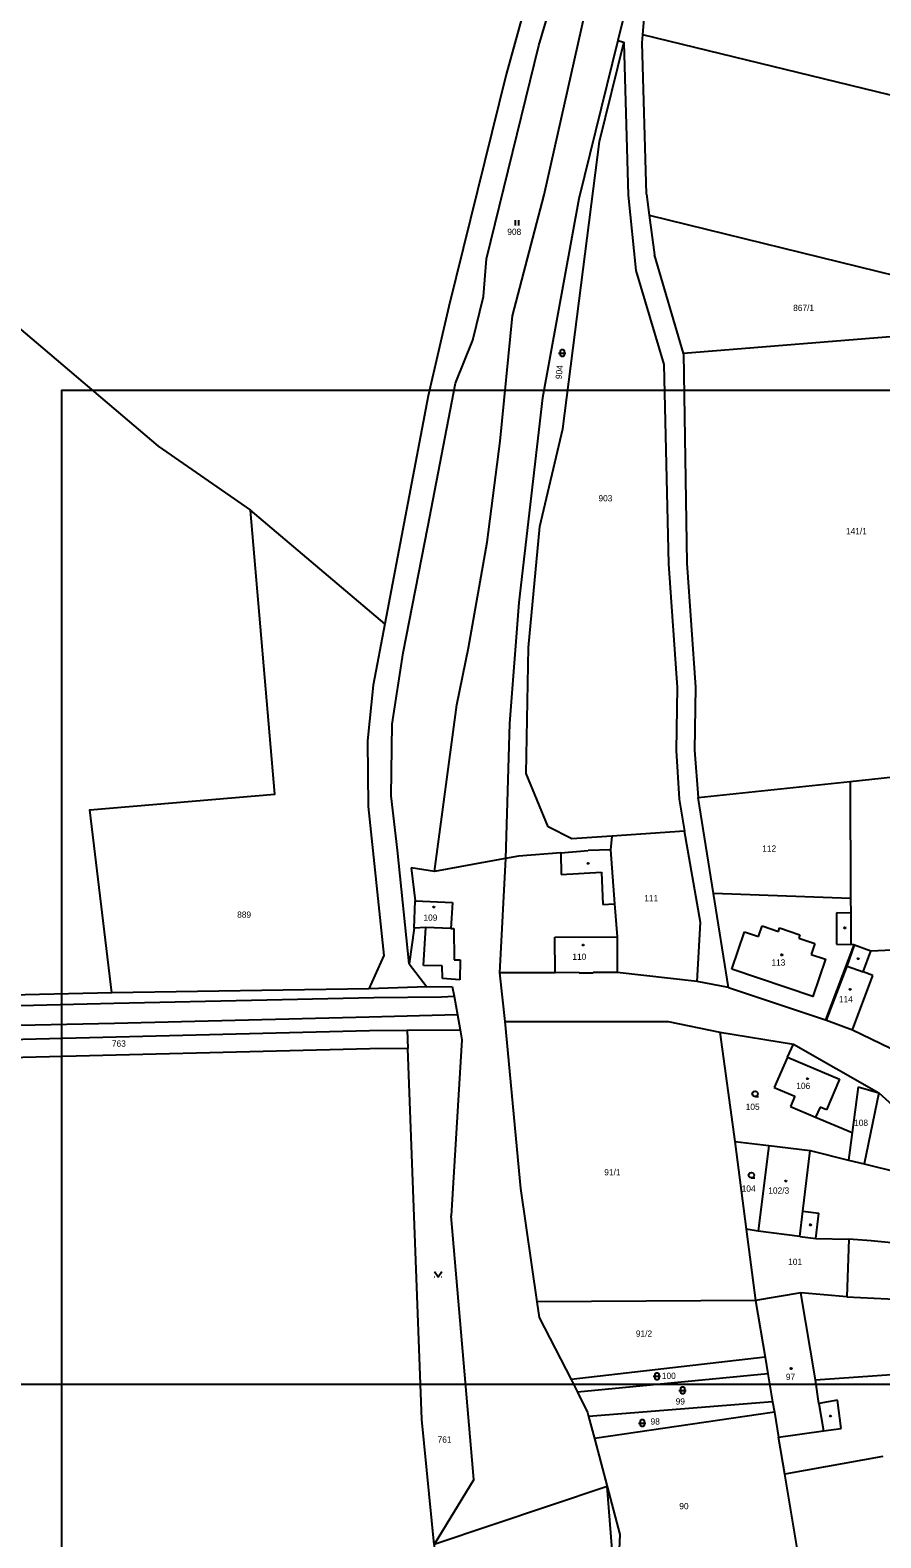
# Model space of a CAD drawing. Extents: x -812394 to -807601, y -1013097 to -1009266.
# Drawn here: x -810008.6 to -809776.7, y -1010812.8 to -1010401.8 of the extents above; entities that cross this region are included whole.
import ezdxf

# ---------------------------------------------------------------- set-up
doc = ezdxf.new("R2010")
doc.units = 0
for name, color, linetype in [('Default', 7, 'Continuous'), ('KLADY_ZMVM', 7, 'Continuous'), ('KN_HRANICE', 7, 'Continuous'), ('KN_KULTURY', 7, 'Continuous'), ('KN_PARCELY', 7, 'Continuous'), ('KN_SLUCKY', 7, 'Continuous'), ('LEGENDA', 7, 'Continuous'), ('obvod_stavby', 7, 'Continuous')]:
    doc.layers.add(name, color=color, linetype=linetype)

# ---------------------------------------------------------------- blocks, each defined once
blk = doc.blocks.new('304')
at = {"layer": 'Default'}
blk.add_lwpolyline([(0, 0), (-0.38, 0.1), (-0.65, 0.37), (-0.75, 0.74), (-0.65, 1.11), (-0.38, 1.38), (-0.01, 1.48), (0.36, 1.38), (0.63, 1.11), (0.73, 0.73), (0.63, 0.35), (0.36, 0.08), (-0.02, -0.02), (0.98, -0.02)], dxfattribs=at)
blk = doc.blocks.new('306')
at = {"layer": 'Default'}
for p, q in [((-0.5, 1.5), (-0.5, 0)), ((0.5, 0), (0.5, 1.5))]:
    blk.add_line(p, q, dxfattribs=at)
blk = doc.blocks.new('314')
at = {"layer": 'Default'}
for p, q in [((-0.95, 0), (-0.85, 0)), ((0.85, 0), (0.95, 0))]:
    blk.add_line(p, q, dxfattribs=at)
blk.add_lwpolyline([(-1, 1.5), (0, 0), (1, 1.5)], dxfattribs=at)
blk = doc.blocks.new('316')
at = {"layer": 'Default'}
for points in [[(-1, 1), (0.27, 1), (1, 1)], [(-0.5, 1.5), (-0.4, 1.79), (-0.15, 1.97), (0.16, 1.97), (0.41, 1.79), (0.51, 1.5), (0.51, 0.5), (0.41, 0.21), (0.16, 0.03), (-0.15, 0.03), (-0.4, 0.21), (-0.5, 0.5), (-0.5, 1.5)]]:
    blk.add_lwpolyline(points, dxfattribs=at)
blk = doc.blocks.new('402')
at = {"layer": 'Default'}
blk.add_lwpolyline([(0.09, 0.15), (0.18, 0), (0.09, -0.15), (-0.09, -0.15), (-0.18, 0), (-0.09, 0.15), (0.09, 0.15)], dxfattribs=at)

msp = doc.modelspace()

# ---------------------------------------------------------------- linework, layer by layer
at = {"layer": 'KLADY_ZMVM'}
msp.add_lwpolyline([(-810000, -1011000), (-810000, -1010500), (-809375, -1010500), (-809375, -1011000), (-809466.04, -1011000)], dxfattribs=at)
at = {"layer": 'KN_HRANICE'}
for p, q in [((-809864.27, -1010361.43), (-809878.82, -1010413.89)), ((-809869.89, -1010406.06), (-809858.75, -1010368.45)), ((-809842.4, -1010380.57), (-809848.37, -1010404.67)), ((-809841.57, -1010403.09), (-809840.96, -1010395.38)), ((-809841.74, -1010405.27), (-809841.57, -1010403.09)), ((-809714.42, -1010434.16), (-809841.57, -1010403.09)), ((-809884.23, -1010464.16), (-809869.89, -1010406.06)), ((-809848.37, -1010404.67), (-809859.05, -1010447.8)), ((-809853.38, -1010432.24), (-809846.74, -1010405.27)), ((-809848.37, -1010404.67), (-809846.74, -1010405.14)), ((-809846.74, -1010405.14), (-809846.74, -1010405.27)), ((-809846.74, -1010405.27), (-809845.6, -1010446.84)), ((-809840.6, -1010446.52), (-809841.74, -1010405.27)), ((-809878.82, -1010413.89), (-809894.45, -1010477.13)), ((-809863.41, -1010510.51), (-809853.38, -1010432.24)), ((-809859.05, -1010447.8), (-809868.93, -1010502.05)), ((-809845.6, -1010446.84), (-809843.49, -1010467.38)), ((-809840.6, -1010446.52), (-809839.82, -1010452.31)), ((-809839.82, -1010452.31), (-809838.38, -1010463.06)), ((-809839.82, -1010452.31), (-809731.16, -1010478.93)), ((-809885.03, -1010474.47), (-809884.23, -1010464.16)), ((-809830.46, -1010490), (-809838.38, -1010463.06)), ((-809843.49, -1010467.38), (-809835.86, -1010493.01)), ((-809894.45, -1010477.13), (-809900.14, -1010501.55)), ((-809887.91, -1010486.35), (-809885.03, -1010474.47)), ((-809892.66, -1010498.08), (-809887.91, -1010486.35)), ((-809763.21, -1010484.53), (-809830.46, -1010490)), ((-809830.46, -1010490), (-809829.59, -1010547.11)), ((-809835.86, -1010493.01), (-809834.59, -1010547.32)), ((-809900.15, -1010537.27), (-809892.66, -1010498.08)), ((-809900.14, -1010501.55), (-809911.91, -1010563.63)), ((-809868.93, -1010502.05), (-809875.4, -1010557.89)), ((-809869.64, -1010537.09), (-809863.41, -1010510.51)), ((-809911.91, -1010563.63), (-809948.53, -1010532.68)), ((-809906.93, -1010571.6), (-809900.15, -1010537.27)), ((-809872.78, -1010570.15), (-809869.64, -1010537.09)), ((-809834.59, -1010547.32), (-809832.23, -1010581.05)), ((-809829.59, -1010547.11), (-809827.23, -1010580.92)), ((-809875.4, -1010557.89), (-809877.92, -1010590.8)), ((-809911.91, -1010563.63), (-809915.08, -1010580.36)), ((-809909.95, -1010591.02), (-809906.93, -1010571.6)), ((-809873.36, -1010604.47), (-809872.78, -1010570.15)), ((-809915.08, -1010580.36), (-809916.6, -1010595.6)), ((-809832.23, -1010581.05), (-809832.51, -1010598.19)), ((-809827.23, -1010580.92), (-809827.51, -1010598.06)), ((-809910.22, -1010610.58), (-809909.95, -1010591.02)), ((-809877.92, -1010590.8), (-809879.03, -1010627.62)), ((-809916.6, -1010595.6), (-809916.47, -1010613.47)), ((-809832.51, -1010598.19), (-809831.62, -1010611.42)), ((-809827.51, -1010598.06), (-809826.5, -1010610.99)), ((-809867.35, -1010619), (-809873.36, -1010604.47)), ((-809785.03, -1010606.6), (-809746.74, -1010602.54)), ((-809826.5, -1010610.99), (-809785.03, -1010606.6)), ((-809785.03, -1010606.6), (-809784.91, -1010638.49)), ((-809916.47, -1010613.47), (-809912.17, -1010654.1)), ((-809908.47, -1010625.32), (-809910.22, -1010610.58)), ((-809831.62, -1010611.42), (-809830.2, -1010620.19)), ((-809822.29, -1010637.21), (-809826.5, -1010610.99)), ((-809860.96, -1010622.27), (-809867.35, -1010619)), ((-809850.01, -1010621.53), (-809860.96, -1010622.27)), ((-809850.01, -1010621.53), (-809850.38, -1010625.24)), ((-809830.2, -1010620.19), (-809850.01, -1010621.53)), ((-809825.85, -1010645.04), (-809830.2, -1010620.19)), ((-809905.25, -1010656.34), (-809908.47, -1010625.32)), ((-809863.92, -1010626.08), (-809875.47, -1010626.99)), ((-809863.92, -1010626.08), (-809856.43, -1010625.49)), ((-809850.38, -1010625.24), (-809856.43, -1010625.49)), ((-809850.38, -1010625.24), (-809849.27, -1010639.96)), ((-809898.33, -1010631.14), (-809904.71, -1010630.14)), ((-809904.71, -1010630.14), (-809903.64, -1010639.2)), ((-809884.55, -1010628.63), (-809898.33, -1010631.14)), ((-809879.03, -1010627.62), (-809884.55, -1010628.63)), ((-809879.03, -1010627.62), (-809880.69, -1010658.8)), ((-809875.47, -1010626.99), (-809879.03, -1010627.62)), ((-809784.91, -1010638.49), (-809822.29, -1010637.21)), ((-809818.18, -1010662.82), (-809822.29, -1010637.21)), ((-809784.91, -1010638.49), (-809784.89, -1010642.49)), ((-809903.91, -1010646.62), (-809903.64, -1010639.2)), ((-809903.64, -1010639.2), (-809893.45, -1010639.62)), ((-809893.45, -1010639.62), (-809893.9, -1010646.74)), ((-809849.27, -1010639.96), (-809848.59, -1010648.97)), ((-809784.89, -1010642.49), (-809784.86, -1010651.09)), ((-809903.91, -1010646.62), (-809905.25, -1010656.34)), ((-809900.74, -1010646.45), (-809903.91, -1010646.62)), ((-809901.36, -1010656.81), (-809900.74, -1010646.45)), ((-809893.9, -1010646.74), (-809893.14, -1010646.74)), ((-809893.14, -1010646.74), (-809892.97, -1010655.26)), ((-809826.78, -1010661.18), (-809825.85, -1010645.04)), ((-809848.59, -1010648.97), (-809848.53, -1010658.67)), ((-809912.17, -1010654.1), (-809916.25, -1010663.18)), ((-809784.01, -1010651.14), (-809791.73, -1010671.61)), ((-809784.01, -1010651.14), (-809784.86, -1010651.09)), ((-809783.82, -1010651.21), (-809784.01, -1010651.14)), ((-809779.36, -1010652.87), (-809783.82, -1010651.21)), ((-809773.49, -1010652.65), (-809779.36, -1010652.87)), ((-809905.25, -1010656.34), (-809900.5, -1010662.65)), ((-809896.28, -1010656.85), (-809901.36, -1010656.81)), ((-809896.15, -1010660.38), (-809896.28, -1010656.85)), ((-809892.97, -1010655.26), (-809891.34, -1010655.24)), ((-809891.34, -1010655.24), (-809891.49, -1010660.73)), ((-809865.45, -1010658.79), (-809880.69, -1010658.8)), ((-809880.69, -1010658.8), (-809879.15, -1010672.04)), ((-809858.96, -1010658.74), (-809865.45, -1010658.79)), ((-809858.96, -1010658.89), (-809858.96, -1010658.74)), ((-809855.08, -1010658.87), (-809858.96, -1010658.89)), ((-809848.53, -1010658.67), (-809855.08, -1010658.72)), ((-809855.08, -1010658.72), (-809855.08, -1010658.87)), ((-809826.78, -1010661.18), (-809848.53, -1010658.67)), ((-809916.25, -1010663.18), (-809986.36, -1010664.25)), ((-809900.5, -1010662.65), (-809916.25, -1010663.18)), ((-809900.5, -1010662.65), (-809893.53, -1010662.52)), ((-809891.49, -1010660.73), (-809896.15, -1010660.38)), ((-809893.53, -1010662.52), (-809893.05, -1010665.19)), ((-809818.18, -1010662.82), (-809826.78, -1010661.18)), ((-809818.18, -1010662.82), (-809791.73, -1010671.61)), ((-809986.36, -1010664.25), (-810055.49, -1010665.89)), ((-809893.05, -1010665.19), (-809892.14, -1010670.27)), ((-809892.14, -1010670.27), (-809891.41, -1010674.3)), ((-810054.08, -1010677.99), (-809916.11, -1010674.55)), ((-809916.11, -1010674.55), (-809905.86, -1010674.45)), ((-809905.86, -1010674.45), (-809891.41, -1010674.3)), ((-809905.86, -1010674.45), (-809905.67, -1010679.45)), ((-809891.41, -1010674.3), (-809890.92, -1010677.02)), ((-809879.15, -1010672.04), (-809834.64, -1010672.02)), ((-809879.15, -1010672.04), (-809874.93, -1010717.6)), ((-809834.64, -1010672.02), (-809820.53, -1010674.93)), ((-809820.53, -1010674.93), (-809816.51, -1010704.77)), ((-809820.53, -1010674.93), (-809800.51, -1010678.2)), ((-809791.73, -1010671.61), (-809791.45, -1010671.71)), ((-809791.45, -1010671.71), (-809784.4, -1010674.33)), ((-809784.4, -1010674.33), (-809774.04, -1010679.33)), ((-809916.02, -1010679.55), (-810053.85, -1010682.99)), ((-809905.67, -1010679.45), (-809916.02, -1010679.55)), ((-809901.85, -1010780.54), (-809905.67, -1010679.45)), ((-809890.92, -1010677.02), (-809893.8, -1010725.05)), ((-809802.14, -1010681.76), (-809800.51, -1010678.2)), ((-809800.51, -1010678.2), (-809777.22, -1010691.48)), ((-809802.14, -1010681.76), (-809805.72, -1010690.09)), ((-809805.72, -1010690.09), (-809800.16, -1010692.42)), ((-809782.82, -1010689.83), (-809784.46, -1010702.29)), ((-809782.82, -1010689.83), (-809777.22, -1010691.48)), ((-809777.22, -1010691.48), (-809781.21, -1010710.87)), ((-809777.22, -1010691.48), (-809766.01, -1010701.62)), ((-809800.16, -1010692.42), (-809801.34, -1010695.22)), ((-809801.34, -1010695.22), (-809794.45, -1010698.17)), ((-809794.45, -1010698.17), (-809784.46, -1010702.29)), ((-809784.46, -1010702.29), (-809785.46, -1010709.82)), ((-809816.51, -1010704.77), (-809813.43, -1010728.67)), ((-809816.51, -1010704.77), (-809807.17, -1010705.86)), ((-809807.17, -1010705.86), (-809810.15, -1010729.19)), ((-809807.17, -1010705.86), (-809795.91, -1010707.24)), ((-809797.91, -1010723.76), (-809795.91, -1010707.24)), ((-809795.91, -1010707.24), (-809785.46, -1010709.82)), ((-809785.46, -1010709.82), (-809781.21, -1010710.87)), ((-809781.21, -1010710.87), (-809771.66, -1010713.22)), ((-809874.93, -1010717.6), (-809870.46, -1010748.48)), ((-809798.74, -1010730.64), (-809797.91, -1010723.76)), ((-809887.66, -1010796.86), (-809893.8, -1010725.05)), ((-809813.43, -1010728.67), (-809810.87, -1010748.08)), ((-809810.15, -1010729.19), (-809813.43, -1010728.67)), ((-809798.74, -1010730.64), (-809810.15, -1010729.19)), ((-809798.74, -1010730.64), (-809794.37, -1010731.2)), ((-809794.37, -1010731.2), (-809785.42, -1010731.43)), ((-809785.42, -1010731.43), (-809785.91, -1010747.13)), ((-809779.32, -1010731.85), (-809785.42, -1010731.43)), ((-809752.63, -1010734.46), (-809779.32, -1010731.85)), ((-809810.87, -1010748.08), (-809870.46, -1010748.48)), ((-809870.46, -1010748.48), (-809869.85, -1010752.77)), ((-809798.52, -1010745.99), (-809810.87, -1010748.08)), ((-809810.87, -1010748.08), (-809808.24, -1010763.58)), ((-809785.91, -1010747.13), (-809798.52, -1010745.99)), ((-809794.5, -1010769.7), (-809798.52, -1010745.99)), ((-809785.91, -1010747.13), (-809765.89, -1010748.07)), ((-809869.85, -1010752.77), (-809861.14, -1010769.64)), ((-809808.24, -1010763.58), (-809861.14, -1010769.64)), ((-809808.24, -1010763.58), (-809807.48, -1010768.06)), ((-809861.14, -1010769.64), (-809859.41, -1010773.1)), ((-809807.48, -1010768.06), (-809859.41, -1010773.1)), ((-809807.48, -1010768.06), (-809806.19, -1010775.7)), ((-809794.5, -1010769.7), (-809750.96, -1010766.66)), ((-809793.54, -1010776.17), (-809794.5, -1010769.7)), ((-809859.41, -1010773.1), (-809856.66, -1010778.59)), ((-809806.19, -1010775.7), (-809856.35, -1010779.75)), ((-809806.19, -1010775.7), (-809805.71, -1010778.53)), ((-809788.53, -1010775.31), (-809793.54, -1010776.17)), ((-809787.51, -1010782.96), (-809788.53, -1010775.31)), ((-809898.47, -1010814.6), (-809901.85, -1010780.54)), ((-809856.66, -1010778.59), (-809856.35, -1010779.75)), ((-809856.35, -1010779.75), (-809854.75, -1010785.76)), ((-809805.71, -1010778.53), (-809854.75, -1010785.76)), ((-809805.71, -1010778.53), (-809804.56, -1010785.33)), ((-809854.75, -1010785.76), (-809847.8, -1010811.91)), ((-809804.56, -1010785.33), (-809792.3, -1010783.63)), ((-809802.82, -1010795.47), (-809804.56, -1010785.33)), ((-809792.3, -1010783.63), (-809787.51, -1010782.96)), ((-809776.12, -1010790.59), (-809802.82, -1010795.47)), ((-809887.66, -1010796.86), (-809898.47, -1010814.6)), ((-809795, -1010842.25), (-809802.82, -1010795.47)), ((-809847.8, -1010811.91), (-809848.47, -1010824.63))]:
    msp.add_line(p, q, dxfattribs=at)
for points in [[(-810125.58, -1010268.83), (-810098.76, -1010346.96), (-810085.55, -1010386.62), (-810074.48, -1010407.06), (-810047.35, -1010444.71), (-810013.62, -1010481.33), (-809973.7, -1010515.27), (-809948.53, -1010532.68)], [(-809898.33, -1010631.14), (-809892.3, -1010585.73), (-809889.06, -1010570.22), (-809883.97, -1010541.36), (-809880.44, -1010513.89), (-809877.14, -1010479.74), (-809868.51, -1010446.75), (-809850.96, -1010368.61), (-809838.06, -1010317.02)], [(-809986.36, -1010664.25), (-809992.37, -1010614.33), (-809941.93, -1010610.06), (-809948.53, -1010532.68)]]:
    msp.add_lwpolyline(points, dxfattribs=at)
at = {"layer": 'KN_SLUCKY'}
for p, q in [((-809863.92, -1010626.08), (-809863.87, -1010631.99)), ((-809863.87, -1010631.99), (-809852.85, -1010631.39)), ((-809852.85, -1010631.39), (-809852.45, -1010640.17)), ((-809852.45, -1010640.17), (-809849.27, -1010639.96)), ((-809788.76, -1010642.46), (-809788.8, -1010650.98)), ((-809784.89, -1010642.49), (-809788.76, -1010642.46)), ((-809893.9, -1010646.74), (-809900.74, -1010646.45)), ((-809810.03, -1010648.9), (-809809.06, -1010645.99)), ((-809809.06, -1010645.99), (-809804.61, -1010647.48)), ((-809804.61, -1010647.48), (-809804.3, -1010646.54)), ((-809804.3, -1010646.54), (-809798.72, -1010648.4)), ((-809865.55, -1010649.04), (-809848.59, -1010648.97)), ((-809865.45, -1010658.79), (-809865.55, -1010649.04)), ((-809817.34, -1010657.79), (-809813.83, -1010647.63)), ((-809813.83, -1010647.63), (-809810.03, -1010648.9)), ((-809798.72, -1010648.4), (-809799.03, -1010649.34)), ((-809799.03, -1010649.34), (-809794.68, -1010650.8)), ((-809794.68, -1010650.8), (-809795.68, -1010653.8)), ((-809788.8, -1010650.98), (-809784.86, -1010651.09)), ((-809785.89, -1010656.93), (-809783.82, -1010651.21)), ((-809781.46, -1010658.5), (-809779.36, -1010652.87)), ((-809791.45, -1010671.71), (-809785.89, -1010656.93)), ((-809785.89, -1010656.93), (-809781.46, -1010658.5)), ((-809778.83, -1010659.48), (-809781.46, -1010658.5)), ((-809784.4, -1010674.33), (-809778.83, -1010659.48)), ((-809802.14, -1010681.76), (-809787.93, -1010687.73)), ((-809787.93, -1010687.73), (-809791.51, -1010696.11)), ((-809793.26, -1010695.37), (-809794.45, -1010698.17)), ((-809791.51, -1010696.11), (-809793.26, -1010695.37)), ((-809797.91, -1010723.76), (-809793.59, -1010724.28)), ((-809794.37, -1010731.2), (-809793.59, -1010724.28)), ((-809793.54, -1010776.17), (-809792.3, -1010783.63))]:
    msp.add_line(p, q, dxfattribs=at)
for points in [[(-809795.68, -1010653.8), (-809791.74, -1010655.11), (-809795.22, -1010665.26), (-809817.34, -1010657.79)], [(-810344.19, -1010752.53), (-810273.06, -1010722.45), (-810248.7, -1010712.3), (-810223.92, -1010702.34), (-810206.13, -1010696.21), (-810185.44, -1010689.81), (-810156.57, -1010681.91), (-810134.5, -1010676.73), (-810114.72, -1010672.98), (-810109.79, -1010672.48), (-810091.32, -1010670.68), (-810055.35, -1010668.8), (-809985.8, -1010667.08), (-809914.9, -1010665.54), (-809896.43, -1010665.35), (-809893.05, -1010665.19)], [(-809892.14, -1010670.27), (-809916.16, -1010670.87), (-809985.6, -1010672.61), (-810054.88, -1010674.08), (-810090.2, -1010675.82), (-810114.86, -1010678.42), (-810132.89, -1010681.81), (-810155.25, -1010686.99), (-810183.11, -1010694.54), (-810204.51, -1010701.07), (-810221.88, -1010707.31), (-810247.24, -1010717.56), (-810270.76, -1010727.41), (-810342.3, -1010757.12)]]:
    msp.add_lwpolyline(points, dxfattribs=at)
at = {"layer": 'LEGENDA'}
msp.add_lwpolyline([(-810040.19, -1011191.03), (-809446.19, -1011191.03), (-809446.19, -1010771.03), (-810040.19, -1010771.03)], close=True, dxfattribs=at)
at = {"layer": 'obvod_stavby'}
msp.add_lwpolyline([(-809819.54, -1010907.68), (-809820.27, -1010877.38), (-809829.44, -1010832), (-809848.49, -1010834.46), (-809851.28, -1010798.84), (-809898.47, -1010814.6), (-809898.21, -1010828.41), (-809894.78, -1010861.65), (-809893.92, -1010865.41), (-809892.39, -1010868.68), (-809890.33, -1010872.36)], dxfattribs=at)

# ---------------------------------------------------------------- block references
at = {"layer": 'KN_KULTURY'}
for name, p in [('306', (-809875.85, -1010455.12)), ('316', (-809863.55, -1010490.87)), ('402', (-809856.47, -1010628.94)), ('402', (-809898.57, -1010640.86)), ('402', (-809786.45, -1010646.52)), ('402', (-809857.81, -1010651.2)), ('402', (-809803.7, -1010653.89)), ('402', (-809782.84, -1010654.95)), ('402', (-809785.08, -1010663.3)), ('402', (-809796.68, -1010687.62)), ('304', (-809810.97, -1010692.52)), ('304', (-809811.97, -1010714.65)), ('402', (-809802.61, -1010715.55)), ('402', (-809795.87, -1010727.49)), ('314', (-809897.39, -1010741.68)), ('316', (-809837.72, -1010769.76)), ('402', (-809801.13, -1010766.65)), ('316', (-809830.72, -1010773.59)), ('316', (-809841.72, -1010782.52)), ('402', (-809790.39, -1010779.57))]:
    msp.add_blockref(name, p, dxfattribs=at)

# ---------------------------------------------------------------- texts
at = {"layer": 'KN_PARCELY'}
for s, p in [('908', (-809878.52, -1010457.66)), ('867/1', (-809800.58, -1010478.4)), ('903', (-809853.67, -1010530.29)), ('141/1', (-809786.18, -1010539.25)), ('112', (-809809.01, -1010625.77)), ('111', (-809841.17, -1010639.28)), ('889', (-809952.18, -1010643.78)), ('109', (-809901.38, -1010644.6)), ('110', (-809860.78, -1010655.25)), ('113', (-809806.51, -1010656.83)), ('114', (-809788.11, -1010666.82)), ('763', (-809986.33, -1010678.91)), ('106', (-809799.72, -1010690.45)), ('105', (-809813.52, -1010696.15)), ('108', (-809783.96, -1010700.5)), ('91/1', (-809852.08, -1010714)), ('104', (-809814.62, -1010718.45)), ('102/3', (-809807.36, -1010718.99)), ('101', (-809801.95, -1010738.42)), ('91/2', (-809843.46, -1010757.98)), ('100', (-809836.38, -1010769.49)), ('97', (-809802.56, -1010769.74)), ('99', (-809832.61, -1010776.46)), ('98', (-809839.46, -1010781.92)), ('761', (-809897.52, -1010786.85)), ('90', (-809831.62, -1010805))]:
    msp.add_text(s, height=1.7, dxfattribs=at).set_placement(p)
msp.add_text('904', height=1.7, rotation=84.74, dxfattribs=at).set_placement((-809863.69, -1010497.03))

doc.saveas('drawing.dxf')
